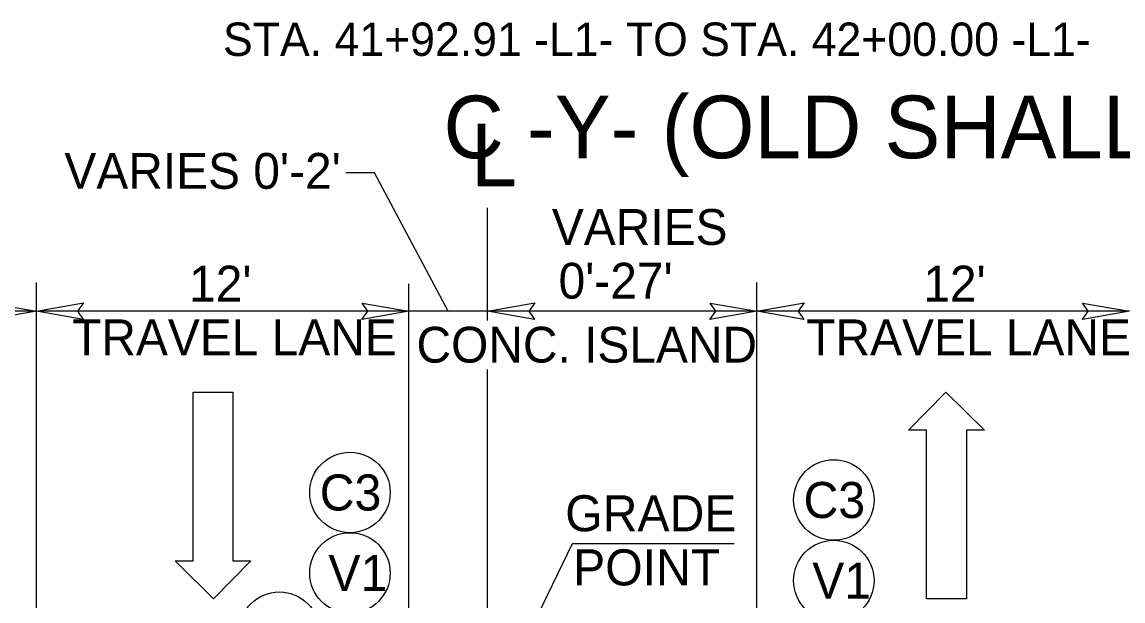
# Model space of a CAD drawing. Extents: x 2176024 to 2177225, y 75947 to 76635.
# Drawn here: x 2176754.66 to 2176790.13, y 76478.59 to 76497.23 of the extents above; entities that cross this region are included whole.
import ezdxf

# ---------------------------------------------------------------- set-up
doc = ezdxf.new("R2010")
doc.units = 0
for name, color, linetype in [('Old_Level_11', 7, 'Continuous'), ('Old_Level_4', 7, 'Continuous'), ('Prop Dimension', 7, 'Continuous'), ('Typical Terminator CELL', 7, 'Continuous'), ('Typical Text General CELL', 7, 'Continuous'), ('Typical Text Label CELL', 7, 'Continuous')]:
    doc.layers.add(name, color=color, linetype=linetype)

msp = doc.modelspace()

# ---------------------------------------------------------------- linework, layer by layer
at = {"layer": 'Old_Level_11'}
for p, q in [((2176772.383, 76480.431), (2176769.659, 76474.823)), ((2176777.602, 76480.431), (2176772.383, 76480.431))]:
    msp.add_line(p, q, dxfattribs=at)
for centre in [(2176765.227, 76482.086), (2176780.811, 76481.844), (2176765.227, 76479.494), (2176780.811, 76479.252), (2176762.954, 76477.589)]:
    msp.add_circle(centre, 1.296, dxfattribs=at)
at = {"layer": 'Old_Level_4'}
for p, q in [((2176760.176, 76479.882), (2176760.176, 76485.314)), ((2176760.176, 76485.314), (2176761.456, 76485.314)), ((2176761.456, 76485.314), (2176761.456, 76479.882)), ((2176783.22, 76484.092), (2176784.423, 76485.314)), ((2176784.423, 76485.314), (2176785.665, 76484.092)), ((2176783.802, 76484.092), (2176783.22, 76484.092)), ((2176783.802, 76478.66), (2176783.802, 76484.092)), ((2176785.665, 76484.092), (2176785.083, 76484.092)), ((2176785.083, 76484.092), (2176785.083, 76478.66)), ((2176760.835, 76478.66), (2176759.594, 76479.882)), ((2176759.594, 76479.882), (2176760.176, 76479.882)), ((2176762.038, 76479.882), (2176760.835, 76478.66)), ((2176761.456, 76479.882), (2176762.038, 76479.882)), ((2176785.083, 76478.66), (2176783.802, 76478.66))]:
    msp.add_line(p, q, dxfattribs=at)
at = {"layer": 'Prop Dimension'}
for p, q in [((2176766.02, 76492.376), (2176765.097, 76492.376)), ((2176768.394, 76487.916), (2176766.02, 76492.376)), ((2176769.659, 76487.616), (2176769.659, 76491.246)), ((2176755.129, 76475.033), (2176755.129, 76488.844)), ((2176767.129, 76476.103), (2176767.129, 76488.801)), ((2176778.335, 76476.179), (2176778.335, 76488.844)), ((2176778.335, 76476.103), (2176778.335, 76488.801)), ((2176755.129, 76487.916), (2176743.235, 76487.916)), ((2176767.129, 76487.916), (2176755.235, 76487.916)), ((2176769.659, 76487.916), (2176767.129, 76487.916)), ((2176778.335, 76487.916), (2176769.659, 76487.916)), ((2176790.335, 76487.916), (2176778.335, 76487.916)), ((2176769.659, 76466.884), (2176769.659, 76486.042))]:
    msp.add_line(p, q, dxfattribs=at)
at = {"layer": 'Typical Terminator CELL'}
for points in [[(2176753.619, 76488.176), (2176755.129, 76487.916), (2176753.611, 76487.648), (2176753.804, 76487.916)], [(2176756.639, 76487.656), (2176755.129, 76487.916), (2176756.647, 76488.184), (2176756.454, 76487.916)], [(2176765.619, 76488.176), (2176767.129, 76487.916), (2176765.611, 76487.648), (2176765.804, 76487.916)], [(2176771.169, 76487.656), (2176769.659, 76487.916), (2176771.177, 76488.184), (2176770.985, 76487.916)], [(2176776.825, 76488.176), (2176778.335, 76487.916), (2176776.817, 76487.648), (2176777.009, 76487.916)], [(2176779.844, 76487.656), (2176778.335, 76487.916), (2176779.853, 76488.184), (2176779.66, 76487.916)], [(2176788.825, 76488.176), (2176790.335, 76487.916), (2176788.817, 76487.648), (2176789.009, 76487.916)]]:
    msp.add_lwpolyline(points, close=True, dxfattribs=at)

# ---------------------------------------------------------------- texts
at = {"layer": 'Old_Level_11'}
for s, rotation, p in [('C3', 0.0003, (2176764.255, 76481.506)), ('C3', 0.0003, (2176779.838, 76481.264)), ('GRADE', 0.0002, (2176772.161, 76480.836)), ('POINT', 0.0002, (2176772.414, 76479.096)), ('V1', 0.0003, (2176764.534, 76478.914)), ('V1', 0.0003, (2176780.117, 76478.672))]:
    msp.add_text(s, height=1.16, rotation=rotation, dxfattribs=at).set_placement(p)
at = {"layer": 'Typical Text General CELL'}
for s, height, p in [("VARIES 0'-2'", 1.15334, (2176756.029, 76491.858)), ('VARIES', 1.1533, (2176771.731, 76490.054)), ("0'-27'", 1.1533, (2176771.947, 76488.324)), ("12'", 1.1533, (2176760.047, 76488.232)), ("12'", 1.1533, (2176783.695, 76488.232)), ('TRAVEL LANE', 1.15334, (2176756.278, 76486.502)), ('TRAVEL LANE', 1.15334, (2176779.925, 76486.502)), ('CONC. ISLAND', 1.15334, (2176767.371, 76486.265))]:
    msp.add_text(s, height=height, dxfattribs=at).set_placement(p)
at = {"layer": 'Typical Text Label CELL'}
for s, height, p in [('STA. 41+92.91 -L1- TO STA. 42+00.00 -L1-', 1.0742, (2176761.138, 76496.135)), ('C -Y- (OLD SHALLOTTE RD)', 2.01314, (2176768.239, 76492.843))]:
    msp.add_text(s, height=height, dxfattribs=at).set_placement(p)
msp.add_text('L', height=2.013, rotation=359.9469, dxfattribs=at).set_placement((2176769.116, 76491.941))

doc.saveas('drawing.dxf')
